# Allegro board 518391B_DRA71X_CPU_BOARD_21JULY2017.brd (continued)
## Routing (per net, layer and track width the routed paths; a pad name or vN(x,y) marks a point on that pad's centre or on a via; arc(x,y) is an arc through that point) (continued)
MCU_CAN0_STB: length 30.2
  TOP w0.127: U37.29 141.26,48.35 v2(141.73,47.88)
  TOP w0.14: v4(129.54,30.35) 129.16,29.97 U46.8
  BOTTOM w0.127: v4(129.54,30.35) 130.12,30.94 135.58,30.94 138.94,34.29 138.94,38.35 140.72,40.13 140.72,41.78 142.11,43.18 142.11,45.46 141.73,45.85 v2(141.73,47.88)
  BOTTOM w0.14: R383.1 v4(129.54,30.35)
MCU_CAN0_TX: length 9
  TOP w0.127: U37.63 129.36,42.85 129.67,42.54 129.67,38.48 128.65,37.46 U46.1
MCU_CAN2_RX: length 5.7
  TOP w0.127: v2(132.46,37.08) 133.1,37.08 134.73,38.72 U37.10
  BOTTOM w0.127: v2(132.46,37.08) RJ27.1
MCU_CAN2_STB: length 24.6
  TOP w0.127: U37.28 141.13,47.85 142.11,46.86 v2(142.15,46.86) ; v4(137.29,28.19) RJ31.1
  BOTTOM w0.127: v4(137.29,28.19) 137.52,28.42 137.52,32.36 139.32,34.16 139.32,37.97 141.07,39.72 141.07,41.5 142.49,42.93 142.49,46.48 142.15,46.82 v2(142.15,46.86)
MCU_CAN2_TX: length 6.5
  TOP w0.127: v2(133.05,37.85) 133.55,38.35 133.86,38.35 134.23,38.73 U37.9
  BOTTOM w0.127: v2(133.05,37.85) 133.05,35.38 RJ28.1
MCU_DBG_RESETN: length 49.3
  TOP w0.127: v2(109.35,31.88) 108.46,30.99 108.46,30.73 107.7,29.97 107.7,28.96 107.19,28.45 107.19,26.54 106.43,25.78 105.41,25.78 104.65,25.02 104.65,23.24 J15.13
  BOTTOM w0.127: v2(109.35,31.88) 110.62,30.61 118.87,30.61 121.41,33.15 134.62,33.15 136.27,34.8 136.27,39.37 135.89,39.75 R349.2
MCU_DCAN1_RX: length 1.8
  BOTTOM w0.127: R371.2 129.54,35.05 RJ27.3
MCU_DCAN1_STB: length 1.1
  TOP w0.127: R426.2 RJ31.3
MCU_DCAN1_TX: length 2.9
  BOTTOM w0.127: R372.2 128.47,34.47 129.72,34.47 129.92,34.67 RJ28.3
MCU_FLMD0: length 51.5
  TOP w0.127: U37.26 v2(141.08,46.85)
  BOTTOM w0.127: J15.4 107.06,34.67 109.22,32.51 120.02,32.51 121.03,33.53 134.37,33.53 135.76,34.92 135.76,37.85 135.13,38.48 135.13,45.85 135.51,46.23 140.46,46.23 v2(141.08,46.85) 140.22,46.85 R332.1
MCU_FLMD1: length 47.5
  TOP w0.127: J15.6 104.65,33.4 104.65,39.5 104.27,39.88 104.27,44.83 106.43,46.99 v2(106.43,47.75)
  LY3 w0.133: v2(106.43,47.75) 116.97,47.75 118.49,46.23 121.41,46.23 122.05,45.59 124.08,45.59 126.11,47.62 128.65,47.62 129.67,48.64 131.95,48.64 v2(132.46,48.13)
  BOTTOM w0.127: R323.2 R322.1 v2(132.46,48.13)
MCU_LIN_EN: length 39.8
  TOP w0.127: 112.27,34.54 v4(112.27,35.98) ; U37.30 v2(141.05,48.85)
  LY3 w0.133: v4(112.27,35.98) 112.27,35.94 112.78,35.43 115.7,35.43 116.08,35.81 123.56,35.81 127.38,39.64 127.38,42.04 128.4,43.05 131.06,43.05 136.86,48.85 v2(141.05,48.85)
  BOTTOM w0.127: R375.1 v4(112.27,35.98)
MCU_P10_9: length 3.9
  TOP w0.127: U37.54 v2(130.3,47.35)
  BOTTOM w0.127: v2(130.3,47.35) 129.52,48.13 R327.2
MCU_P10_10: length 2.4
  TOP w0.127: U37.55 v2(129.65,46.85)
  BOTTOM w0.127: v2(129.65,46.85) 129.39,47.12 R331.2
MCU_P10_13: length 2.6
  TOP w0.127: U37.58 129.3,45.35 v2(129.67,45.72)
  BOTTOM w0.127: R335.2 129.29,46.1 v2(129.67,45.72)
MCU_P10_14: length 2.4
  TOP w0.127: U37.59 129.54,44.85 129.54,44.84 v2(129.64,44.84)
  BOTTOM w0.127: v2(129.64,44.84) 129.4,45.08 R341.2
MCU_PMIC_POWERHOLD: length 112.3
  TOP w0.127: U37.31 141.55,49.35 v2(142.11,49.91) ; Q2.5 v2(161.8,145.41)
  LY4 w0.133: v2(161.8,145.41) 160.4,144.02 160.4,131.44 159.77,130.81 159.77,125.6 158.5,124.33 158.5,121.28 157.86,120.65 157.86,104.65 154.94,101.73 154.56,101.73 153.92,102.36 152.41,102.36 151.64,101.59 151.64,100.97 151.13,100.46 150.37,100.46 149.61,99.69 149.61,95.12 150.24,94.49 150.24,84.96 147.19,81.91 147.19,61.59 145.29,59.69 145.29,53.09 v2(142.11,49.91)
  BOTTOM w0.127: R319.2 141.6,49.4 v2(142.11,49.91)
MCU_RDY: length 47.2
  TOP w0.127: U37.14 136.73,39.33 136.53,39.12 136.53,38.48 v2(136.91,38.1) ; J15.11 104.65,25.78 104.65,27.69 105.28,28.32 106.43,28.32 107.19,29.08 107.19,29.97 107.82,30.61 107.82,31.37 v2(108.39,31.94)
  BOTTOM w0.127: v2(108.39,31.94) 110.24,30.1 119,30.1 121.67,32.77 134.87,32.77 136.91,34.8 v2(136.91,38.1)
MCU_RESETN: length 9
  TOP w0.127: U37.20 v2(141.7,43.85)
  BOTTOM w0.127: v2(141.7,43.85) 140.98,43.85 140.89,43.94 C498.2 R345.1 R349.1
MCU_RLIN30RX: length 2.5
  TOP w0.127: v2(132.97,41.78) 133.24,41.52 U37.7
  BOTTOM w0.127: R356.2 132.72,41.53 v2(132.97,41.78)
MCU_RLIN30TX: length 3.2
  TOP w0.127: U37.6 132.74,41.38 132.33,41.78 v2(131.57,41.78)
  BOTTOM w0.127: R357.2 v2(131.57,41.78)
MCU_RLIN31RX: length 24.1
  TOP w0.127: 113.54,34.54 v4(113.54,35.94) ; U37.56 v2(126.88,46.35)
  LY3 w0.133: v2(126.88,46.35) 126.41,45.88 126.41,41.32 124.55,39.46 122.77,39.46 120.65,37.34 114.94,37.34 v4(113.54,35.94)
  BOTTOM w0.127: R374.2 v4(113.54,35.94)
MCU_RLIN31TX: length 30.1
  TOP w0.127: U37.57 126.49,45.85 v2(125.98,46.35) ; v2(110.11,44.96) 110.11,41.4 108.97,40.26 108.97,36.7 109.73,35.94 109.73,34.54
  BOTTOM w0.127: v2(125.98,46.35) 125.35,45.72 114.81,45.72 114.05,44.96 v2(110.11,44.96)
MCU_SCL: length 35.4
  TOP w0.127: U38.6 v2(108.08,42.16) 108.58,41.66 108.58,40 108.46,39.88 v2(108.46,37.85) ; U37.1 v2(130.24,38.86)
  BOTTOM w0.127: v2(108.08,42.16) R350.2 ; v2(108.46,37.85) 109.85,37.85 110.11,38.1 114.3,38.1 116.79,35.61 117.93,35.61 118.11,35.43 121.79,35.43 124.75,38.39 124.75,39.66 125.9,40.81 128.36,40.81 130.24,38.93 v2(130.24,38.86)
MCU_SDA: length 24.7
  TOP w0.127: U37.64 v2(128.24,41.68) ; U38.5 v2(108.08,40.89)
  BOTTOM w0.127: R351.2 v2(108.08,40.89) 109.6,42.42 114.81,42.42 115.32,41.91 117.73,41.91 118.24,42.42 126.24,42.42 126.97,41.68 v2(128.24,41.68)
MCU_SPI1_SI: length 2.9
  TOP w0.127: U37.53 130.02,47.85 v2(130.3,48.13)
  BOTTOM w0.127: v2(130.3,48.13) R323.1
MCU_TCK: length 41.4
  TOP w0.127: v2(130.3,42.35) 138.06,42.35 138.16,42.25 138.5,42.25 138.6,42.35 U37.17
  BOTTOM w0.127: v2(130.3,42.35) 129.1,41.15 125.86,41.15 124.5,39.79 124.5,38.65 121.67,35.81 118.36,35.81 118.24,35.94 116.97,35.94 114.43,38.48 104.65,38.48 J15.1
MCU_TDI: length 62.2
  TOP w0.127: U37.19 141.05,43.35 v2(141.1,43.31)
  BOTTOM w0.127: J15.7 102.62,29.59 100.71,27.69 100.71,24.89 102.36,23.24 106.43,23.24 107.57,24.38 107.57,26.03 109.51,27.98 119.8,27.98 123.06,31.24 135.38,31.24 138.56,34.42 138.56,38.61 140.34,40.39 R348.2 v2(141.1,43.31)
MCU_TDO: length 48
  TOP w0.127: v2(138.33,42.67) 138.51,42.85 U37.18
  BOTTOM w0.127: v2(138.33,42.67) 137.46,41.81 137.46,39.64 137.67,39.43 137.67,38.73 137.79,38.61 137.79,34.67 135.13,32 122.3,32 119.38,29.08 108.33,29.08 106.55,30.86 104.65,30.86 J15.5
MCU_TMS: length 47.2
  TOP w0.127: v2(138.18,39.05) 137.73,39.49 U37.16
  BOTTOM w0.127: R391.1 101.6,25.78 106.81,25.78 109.47,28.45 119.51,28.45 122.68,31.62 135.25,31.62 138.18,34.54 v2(138.18,39.05) R354.2
MCU_TRSTN: length 46.7
  TOP w0.127: v2(137.03,38.86) 137.23,39.06 U37.15
  BOTTOM w0.127: 101.47,33.53 106.05,33.53 109.98,29.59 119.25,29.59 122.05,32.38 135,32.38 137.41,34.8 137.41,38.48 v2(137.03,38.86) 136.78,39.12 R355.1
MCU_TVD: length 6.6
  TOP w0.305: v2(109.73,33.02) 108.46,33.02 107.19,31.75 107.19,30.86 J15.8
  BOTTOM w0.305: v2(109.73,33.02) R376.1
MCU_WP: length 38.1
  TOP w0.127: v2(131.06,45.97) 132.44,47.35 U37.27 ; U38.7 v2(108.08,43.43)
  BOTTOM w0.127: v2(131.06,45.97) 131.06,44.2 130.3,43.43 126.49,43.43 126.11,43.81 123.19,43.81 122.56,43.18 118.24,43.18 117.35,42.29 115.59,42.29 114.45,43.43 v2(108.08,43.43) R347.1
MCU_X1: length 6.8
  TOP w0.127: X1.2 v2(143.77,47.49) 142.63,46.35 U37.25
  BOTTOM w0.127: C493.1 144.52,47.49 v2(143.77,47.49)
MCU_X2: length 2.8
  TOP w0.127: U37.24 141.73,45.85 141.86,45.72 R130.2
MDIO_MDCLK: length 54.3
  TOP w0.127: v2(116.71,42.8) 117.12,42.39 U40.1 ; U27.D10 v1(95.24,78.53)
  LY3 w0.133: v2(116.71,42.8) 116.2,43.31 109.35,43.31 108.8,43.86 103.34,43.86 v2(103.25,43.94)
  BOTTOM w0.127: v2(103.25,43.94) 102.83,44.36 102.83,46.41 101.98,47.27 101.98,49.15 98.04,53.09 98.04,57.15 98.93,58.04 98.93,59.56 98.04,60.45 98.04,68.2 96.31,69.93 96.31,74.11 94.87,75.55 94.87,78.17 v1(95.24,78.53)
MDIO_MDIO: length 52.1
  TOP w0.127: U40.36 v2(118.39,44.04) ; U27.C10 v1(95.24,77.88)
  LY3 w0.133: v2(102.36,53.47) 102.62,53.72 102.62,58.42 101.98,59.05 101.98,68.83 98.09,72.73 98.09,73.87 95.63,76.33 95.63,77.49 v1(95.24,77.88)
  BOTTOM w0.127: v2(102.36,53.47) 105.03,50.8 105.41,50.8 107.31,48.89 107.31,46.35 108.08,45.59 108.58,45.59 109.98,44.2 114.05,44.2 115.19,45.34 117.35,45.34 117.73,44.96 117.73,44.7 v2(118.39,44.04) 118.42,44.07 R344.2
MMC2_CLK: length 27.2
  TOP w0.127: R99.1 106.05,64.05 105.9,63.9 105.56,63.9 105.41,63.75 105.41,63.54 105.56,63.39 105.9,63.39 106.05,63.25 106.05,63.04 105.9,62.89 105.56,62.89 105.41,62.74 105.41,62.53 105.56,62.38 105.9,62.38 v2(107.82,60.45)
  LY3 w0.133: v2(107.82,60.45) 111.89,60.45 112.9,59.44 123.32,59.44 v2(123.44,59.56)
  BOTTOM w0.127: v2(123.44,59.56) R299.1 R300.2
MMC2_CMD: length 45.7
  TOP w0.127: U27.A6 97.51,75.84 100.84,72.51 100.84,71.37 104.27,67.94 104.27,62.1 v2(105.41,60.96) ; U31.P5 v2(123.21,60.41)
  LY3 w0.133: v2(123.21,60.41) 122.74,59.94 113.03,59.94 112.01,60.96 109.33,60.96 109.18,61.12 109.18,62.07 109.02,62.23 108.8,62.23 108.64,62.07 108.64,61.12 108.49,60.96 108.27,60.96 108.11,61.12 108.11,62.07 107.95,62.23 107.73,62.23 107.58,62.07 107.58,61.12 107.42,60.96 107.2,60.96 107.04,61.12 107.04,62.07 106.89,62.23 106.67,62.23 106.51,62.07 106.51,61.12 106.35,60.96 v2(105.41,60.96)
  BOTTOM w0.127: 124.08,60.45 123.25,60.45 v2(123.21,60.41)
MMC2_DAT0: length 45.3
  TOP w0.127: U27.D7 v1(97.19,78.53) ; v2(117.28,68.58) 118.32,68.58 118.47,68.73 118.47,70.72 118.62,70.87 118.83,70.87 118.98,70.72 118.98,68.73 119.38,68.33 119.38,67.04 119.23,66.89 117.43,66.89 117.28,66.74 117.28,66.53 117.43,66.38 119.23,66.38 119.38,66.23 119.38,66.02 119.23,65.87 117.43,65.87 117.28,65.72 117.28,65.47 118.34,64.41 v2(120.2,64.41) U31.K2
  LY3 w0.133: v1(97.19,78.53) 97.6,78.12 97.6,76.89 102.61,71.89 103.24,71.89 106.17,68.96 116.9,68.96 v2(117.28,68.58)
  BOTTOM w0.127: R273.2 120.18,64.39 v2(120.2,64.41)
MMC2_DAT1: length 45.8
  TOP w0.102: 97.84,78.53 v1(97.84,78.53)
  TOP w0.127: v2(115.06,69.51) 115.66,69.51 115.95,69.21 115.95,67.1 116.1,66.95 116.56,66.95 116.71,66.8 116.71,66.59 116.56,66.44 116.1,66.44 115.95,66.29 115.95,66.08 116.1,65.93 116.56,65.93 116.71,65.79 116.71,65.58 116.56,65.43 116.1,65.43 115.95,65.28 115.95,65.02 116.61,64.37 117.58,64.37 117.73,64.22 117.73,64.01 117.58,63.86 116.61,63.86 116.46,63.71 116.46,63.46 116.61,63.31 118.98,63.31 119.13,63.16 119.13,62.95 118.98,62.8 116.61,62.8 116.46,62.65 116.46,61.85 116.9,61.41 v2(120.2,61.41) U31.N2 ; U27.C6 97.84,78.53
  LY3 w0.133: v1(97.84,78.53) 97.84,78.53 97.84,77.17 102.74,72.26 103.38,72.26 106.16,69.48 115.03,69.48 v2(115.06,69.51)
  BOTTOM w0.127: v2(120.2,61.41) 120.14,61.47 R271.2
MMC2_DAT2: length 45.1
  TOP w0.127: v2(105.41,66.55) 105.41,67.56 101.35,71.63 101.35,72.72 98.16,75.91 U27.A5 ; U31.K3 v2(121.2,64.41)
  LY3 w0.133: v2(105.41,66.55) 106.05,65.91 106.34,65.91 106.49,66.07 106.49,66.77 106.65,66.93 106.87,66.93 107.03,66.77 107.03,66.07 107.18,65.91 107.7,65.91 107.86,65.74 108.1,65.74 108.26,65.9 108.26,66.77 108.41,66.93 108.63,66.93 108.79,66.77 108.79,65.9 108.95,65.74 109.17,65.74 109.32,65.9 109.32,66.77 109.48,66.93 109.7,66.93 109.86,66.77 109.86,65.9 110.01,65.74 110.23,65.74 110.39,65.9 110.39,66.77 110.55,66.93 110.77,66.93 110.92,66.77 110.92,65.9 111.08,65.74 113.45,65.74 114.3,64.9 115.01,64.9 115.17,65.05 115.17,66.39 115.32,66.55 115.55,66.55 115.7,66.39 115.7,65.05 115.86,64.9 116.08,64.9 116.23,65.05 116.23,66.39 116.39,66.55 116.61,66.55 116.77,66.39 116.77,65.05 116.92,64.9 120.72,64.9 v2(121.2,64.41)
  BOTTOM w0.127: v2(121.2,64.41) 121.23,64.39 R269.2
MMC2_DAT3: length 44.9
  TOP w0.102: U27.B6 97.84,77.23 97.84,76.17
  TOP w0.127: v2(104.78,64.39) 104.78,67.82 101.09,71.5 101.09,72.62 97.84,75.87 97.84,76.17 ; U31.N3 v2(121.2,61.41)
  LY3 w0.133: v2(104.78,64.39) 104.78,63.02 104.62,62.86 103.53,62.86 103.38,62.7 103.38,62.48 103.53,62.33 104.62,62.33 104.78,62.17 104.78,62.11 104.91,61.98 105.66,61.98 106.36,62.67 106.36,64.23 106.52,64.39 106.74,64.39 106.9,64.23 106.9,63.15 107.05,62.99 107.27,62.99 107.43,63.15 107.43,64.23 107.59,64.39 108.58,64.39 110.87,62.1 115.57,62.1 116.33,61.34 118.24,61.34 118.75,61.85 120.76,61.85 v2(121.2,61.41)
  BOTTOM w0.127: v2(121.2,61.41) 121.26,61.47 R291.2
MMC2_DAT4: length 46.4
  TOP w0.127: U31.N8 v2(127.21,61.41) ; v2(108.58,59.82) 108.58,60.79 109.14,61.34 109.14,61.55 108.99,61.7 108.78,61.7 108.23,61.15 108.02,61.15 107.87,61.3 107.87,61.51 108.42,62.06 108.42,62.27 108.27,62.42 108.06,62.42 107.51,61.87 107.3,61.87 106.55,62.61 106.55,68.24 98.81,75.98 U27.A4
  LY3 w0.133: v2(127.21,61.41) 127.2,61.41 124.71,58.93 112.78,58.93 111.89,59.82 v2(108.58,59.82)
  BOTTOM w0.127: R289.2 127.02,61.59 v2(127.21,61.41)
MMC2_DAT5: length 43.5
  TOP w0.127: U27.E7 v1(97.19,79.18) ; U31.K8 v2(127.21,64.41)
  LY3 w0.133: v1(97.19,79.18) 96.82,78.81 96.82,76.66 99.19,74.3 99.19,73.79 105.03,67.94 117.16,67.94 117.31,67.79 117.31,66.45 117.47,66.29 117.69,66.29 117.85,66.45 117.85,67.79 118,67.94 118.24,67.94 120.14,66.04 121.54,66.04 123.19,64.39 127.19,64.39 v2(127.21,64.41)
  BOTTOM w0.127: v2(127.21,64.41) 127.06,64.26 126.36,64.26
MMC2_DAT6: length 44.6
  TOP w0.127: v2(106.3,70.4) 108.2,68.49 v2(108.2,63.88) ; U27.D6 v1(97.84,79.18) ; U31.N9 v2(128.21,61.41)
  LY3 w0.133: v2(106.3,70.4) 105.75,70.4 103.51,72.64 102.87,72.64 98.12,77.4 98.12,78.18 98.3,78.36 98.3,78.74 97.85,79.18 v1(97.84,79.18) ; v2(128.21,61.41) 127.79,61.83 126.73,61.83 125.86,60.96 114.68,60.96 114.43,60.71 112.9,60.71 112.01,61.59 110.49,61.59 v2(108.2,63.88)
  BOTTOM w0.127: v2(128.21,61.41) 128.28,61.34 R270.2
MMC2_DAT7: length 43.4
  TOP w0.102: 98.49,77.88 v1(98.49,77.88) 98.49,77.88
  TOP w0.127: U27.C5 v1(98.49,77.88) ; U31.K9 v2(128.21,64.41)
  LY3 w0.133: v1(98.49,77.88) 98.49,77.53 103,73.02 103.63,73.02 105.66,70.99 109.04,70.99 109.17,70.86 111.76,70.86 112.69,69.94 113.24,69.94 113.92,70.61 117.22,70.61 117.37,70.77 117.37,71.47 117.53,71.63 117.75,71.63 117.91,71.47 117.91,70.77 118.06,70.61 118.28,70.61 118.44,70.77 118.44,71.47 118.6,71.63 118.82,71.63 118.97,71.47 118.97,70.77 119.13,70.61 119.38,70.61 119.63,70.36 119.63,67.18 120.4,66.42 121.92,66.42 123.44,64.9 127.72,64.9 v2(128.21,64.41)
  BOTTOM w0.127: v2(128.21,64.41) 128.23,64.39 R268.2
MMC_PWR_ON: length 232.5
  TOP w0.127: U70.3 159,131.19 v2(159.51,131.7) 160.78,131.7 R412.2 ; v1(86.14,82.43) U27.K23
  LY3 w0.133: v2(131.57,97.96) 130.64,97.96 129.79,98.81 105.54,98.81 105.03,99.31 98.42,99.31 89.41,108.33 58.04,108.33 56.64,109.73 47.88,109.73 46.1,107.95 46.1,101.98 45.34,101.22 45.34,95.5 46.48,94.36 46.48,72.77 47.37,71.88 63.25,71.88 64.94,73.57 67.48,73.57 70.36,76.45 73.66,76.45 76.58,79.38 83.08,79.38 84.4,80.7 v1(86.14,82.43)
  LY4 w0.133: v2(159.51,131.7) 159.51,132.08 158.75,132.84 142.24,132.84 131.15,121.75 131.15,101.39 131.57,100.97 v2(131.57,97.96)
NEO_RESETN: length 89.1
  TOP w0.127: U27.H3 v1(99.79,81.78) ; U25.8 v2(167.04,91.49)
  LY3 w0.133: v2(163.32,74.68) 162.95,75.05 155.45,75.05 154.56,75.95 143.89,75.95 143.38,75.44 138.81,75.44 137.79,76.45 137.29,76.45 136.78,75.95 136.64,75.95 136.63,75.95 134.51,75.95 134.51,75.95 134.37,75.95 133.74,75.32 128.14,75.32 127,76.45 122.17,76.45 120.52,78.1 119.13,78.1 118.24,78.99 113.66,78.99 112.78,78.1 106.68,78.1 104.39,80.39 101.98,80.39 100.59,81.78 v1(99.79,81.78)
  LY4 w0.133: v2(163.32,74.68) 163.32,84.33 167.04,88.05 v2(167.04,91.49)
  BOTTOM w0.127: v2(167.04,91.49) 167,91.52 R238.2
NEO_TIMEPULSE: length 128.8
  TOP w0.127: v2(71.78,75.12) 71.67,75.01 R79.2 ; v2(152.27,71.25) 156.59,75.56 165.1,75.56 R68.2 R69.1
  LY3 w0.133: v2(152.27,71.25) 152.27,65.91 148.21,61.85 143.38,61.85 142.88,62.36 137.92,62.36 136.78,61.21 134.11,61.21 131.35,58.45 112.62,58.45 111.88,59.19 109.86,59.19 107.57,56.9 107.57,54.1 105.45,51.99 97.87,51.99 93.85,56.01 93.85,63.12 90.3,66.67 87.88,66.67 87.25,67.31 86.11,67.31 85.85,67.56 76.58,67.56 75.44,68.71 75.44,72.26 73.91,73.79 73.11,73.79 v2(71.78,75.12)
NFAULT: length 151.6
  TOP w0.102: 101.52,81.14 100.44,81.14 U27.H2
  TOP w0.127: D11.2 v2(41.02,104.39) ; v2(116.2,77.22) 116.04,77.38 114,77.38 113.67,77.05 106.06,77.05 105.39,77.72 105.39,77.72 105.26,77.85 101.97,81.14 101.52,81.14 ; U28.26 v2(34.35,92.01)
  LY3 w0.133: v2(93.34,111.12) 100.08,104.39 v2(115.19,104.39)
  LY4 w0.133: v2(115.19,104.39) 115.19,82.42 115.7,81.92 115.7,77.72 v2(116.2,77.22) ; v2(93.34,111.12) 92.58,111.89 82.04,111.89 79.12,114.81 70.61,114.81 68.07,112.27 62.74,112.27 62.48,112.01 55.88,112.01 54.99,112.9 48.91,112.9 46.23,110.22 46.23,109.73 42.42,105.92 41.78,105.92 41.02,105.16 v2(41.02,104.39) 41.91,103.5 41.91,93.85 40.39,92.33 35.05,92.33 34.73,92.01 v2(34.35,92.01)
NMUTE: length 141.7
  TOP w0.127: U27.K5 v1(98.49,82.43) ; U28.25 34.86,91.38 v2(35.05,91.57)
  LY3 w0.133: v2(92.46,111.12) 99.69,103.89 v2(114.55,103.89)
  LY4 w0.133: v2(114.55,103.89) 114.55,102.62 114.18,102.24 114.18,82.68 113.66,82.17 101.6,82.17 100.71,83.06 99.11,83.06 v1(98.49,82.43) ; v2(92.46,111.12) 92.08,111.51 81.66,111.51 78.87,114.3 70.74,114.3 67.18,110.74 53.05,110.74 52.54,111.25 49.91,111.25 49.66,111.51 47.88,111.51 46.74,110.36 46.74,109.73 43.69,106.68 43.69,105.66 42.28,104.26 42.28,93.59 40.64,91.95 35.43,91.95 v2(35.05,91.57)
NSTANDBY: length 139.3
  TOP w0.127: v1(97.84,82.43) U27.K6 ; v2(34.42,90.8) 34.35,90.74 U28.24
  LY3 w0.133: v2(113.92,103.38) 99.19,103.38 v2(91.57,111)
  LY4 w0.133: v1(97.84,82.43) 98.72,83.31 100.96,83.31 101.73,82.55 105.03,82.55 105.66,83.19 112.01,83.19 112.39,82.8 113.66,82.8 113.92,83.06 v2(113.92,103.38) ; v2(91.57,111) 81.41,111 78.61,113.79 70.99,113.79 67.52,110.32 48.88,110.32 42.54,103.99 42.54,93.22 40.89,91.57 36.07,91.57 35.31,90.8 v2(34.42,90.8)
NTRST: length 3.9
  TOP w0.127: J14.9 120.18,52.66 v2(120.52,52.32)
  BOTTOM w0.127: RJ26.3 v2(120.52,52.32) 120.65,52.45 R312.2
NWARN: length 156.5
  TOP w0.127: v2(34.8,92.96) 34.48,92.65 U28.27 ; v1(97.84,81.78) U27.H6 ; D10.2 v2(41.02,106.43)
  LY3 w0.133: v2(94.23,111.12) 100.46,104.9 v2(115.76,104.9) ; v1(97.84,81.78) 98.72,80.9 99.95,80.9 101.6,79.25 103.76,79.25 106.05,76.96 113.66,76.96 114.43,77.72 v2(117.6,77.72)
  LY4 w0.133: v2(117.6,77.72) 116.46,78.87 116.46,82.68 116.2,82.93 116.2,84.96 115.45,85.72 115.45,103.32 115.76,103.63 v2(115.76,104.9) ; v2(34.8,92.96) 39.88,92.96 41.4,94.49 41.4,102.11 40.39,103.12 40.39,105.79 v2(41.02,106.43) 42.42,106.43 45.72,109.73 45.72,110.08 48.92,113.28 68.45,113.28 70.49,115.32 79.38,115.32 82.42,112.27 93.09,112.27 v2(94.23,111.12)
OUT1M: length 5.4
  TOP w0.406: U28.32 19.69,91.38 19.1,91.96 C87.1
OUT1P: length 5.4
  TOP w0.406: U28.34 19.63,90.11 19.1,89.58 C93.1
OUT2M: length 3.3
  TOP w0.406: U28.38 v2(21.91,87.57)
  TOP w0.508: v2(20.32,87.38) 20.35,87.35 v2(21.11,87.35)
  TOP w0.635: v2(21.91,87.57) 21.69,87.35 v2(21.11,87.35)
OUT2P: length 3.3
  TOP w0.406: v2(21.91,86.19) 22.01,86.3 U28.40
  TOP w0.762: v2(21.91,86.19) 21.81,86.19 21.72,86.11 v2(21.08,86.11) 20.45,86.11 v2(20.32,86.23)
OUT3M: length 5.1
  TOP w0.406: U28.45 21.91,83.12 21.84,83.06 19.91,83.06 19.1,83.87 C97.1
OUT3P: length 5.2
  TOP w0.406: U28.47 19.94,81.85 19.1,81.01 C107.1
OUT4M: length 3.3
  TOP w0.406: U28.51 v2(21.91,79.31)
  TOP w0.508: v2(20.45,79.12) 20.56,79.01 v2(21.21,79.01)
  TOP w0.635: v2(21.91,79.31) 21.6,79.01 v2(21.21,79.01)
OUT4P: length 3.4
  TOP w0.406: U28.53 v2(21.91,78.04)
  TOP w0.762: v2(20.37,78.1) 20.63,77.84 v2(21.08,77.84) 21.71,77.84 v2(21.91,78.04)
PG1_PMIC: length 67.5
  TOP w0.127: 74.8,48.77 TP41.1 75.29,50.53 77.38,50.53 77.39,50.53 79.54,50.53 79.54,50.53 v2(81.13,50.53) 81.41,50.53 81.93,51.05 82.58,51.05 83.47,51.95 U32.27
  LY3 w0.133: v2(81.13,50.53) 81.9,50.53 83.29,51.92 87.66,51.92 87.87,51.7 87.87,51.07 89.66,49.28 95.88,49.28 97.04,50.43 120.15,50.43 120.4,50.67 121.79,50.67 122.3,51.18 132.46,51.18 v2(133.22,50.42)
  BOTTOM w0.127: R316.1 v2(133.22,50.42)
PG_LM5141: length 179.6
  TOP w0.127: 73.15,111.76 v2(74.42,111.76)
  TOP w0.203: U18.21 v2(76.59,125.22) ; U42.6 91.31,34.29 v2(92.2,33.4)
  LY3 w0.133: v2(41.87,67.44) 41.91,67.44 42.93,66.42 43.43,66.42 44.45,65.41 45.72,65.41 49.4,61.72 53.72,61.72 v2(54.99,60.45) ; v2(74.42,111.76) 74.42,113.16 76.2,114.94 TP12.1 76.2,124.83 v2(76.59,125.22)
  LY4 w0.133: v2(74.42,111.76) 71.75,109.09 50.55,109.09 47.37,105.92 47.37,104.9 44.02,101.55 44.02,96.55 44.2,96.37 44.2,87.12 43.69,86.61 43.69,81.28 44.44,80.52 44.44,75.05 41.87,72.48 v2(41.87,67.44) ; v2(78.87,135.76) 76.96,133.86 76.96,125.6 76.59,125.23 v2(76.59,125.22)
  BOTTOM w0.127: Q11.2 v2(78.87,135.76) ; v2(92.2,33.4) 90.04,33.4 87.5,30.86 67.69,30.86 56.9,41.66 56.9,57.53 54.99,59.44 v2(54.99,60.45)
  BOTTOM w0.203: v2(76.59,125.22) 76.58,125.22 R217.1
PG_LM5175: length 253.8
  TOP w0.127: v2(132.21,92.16) 132.63,92.58 134.62,92.58 135,92.2 144.36,92.2 v2(144.74,91.82) ; v2(136.92,18.58) 136.92,13.95 138.56,12.32 141.49,12.32 141.84,12.67 U51.3 ; U43.3 v2(145.68,38.86)
  TOP w0.203: TP9.1 v2(58.55,121.28) 56.26,121.28 55.89,120.91 U19.17 ; C63.2 R40.2 v2(58.55,117.35)
  LY3 w0.133: 94.91,138.3 v2(94.91,143.51) ; 94.91,138.3 97.41,138.3 102.74,132.97 v2(132.72,132.97) ; 94.91,138.3 93.51,136.91 70.99,136.91 67.06,132.97 67.06,131.95 60.83,125.73 60.83,124.59 TP9.1 v2(58.55,121.28)
  LY4 w0.133: v2(146.69,76.45) 145.8,77.34 145.8,80.26 144.14,81.91 144.14,90.04 144.74,90.64 v2(144.74,91.82) ; v2(132.21,92.16) 132.21,93.85 131.06,95 131.06,95.88 130.68,96.27 130.68,100.33 130.43,100.58 130.43,122.43 132.72,124.71 v2(132.72,132.97)
  BOTTOM w0.127: v2(136.92,18.58) 140.59,22.25 140.59,24.38 141.35,25.15 141.35,31.62 142.96,33.24 142.96,36.14 v2(145.68,38.86) 145.68,39.99 143.22,42.46 143.22,48.22 144.53,49.53 144.53,60.2 148.34,64.01 148.34,65.28 149.22,66.17 149.22,70.23 147.32,72.14 147.32,75.82 v2(146.69,76.45) ; R208.1 94.49,143.93 v2(94.91,143.51)
  BOTTOM w0.203: v2(58.55,121.28) v2(58.55,117.35)
PG_LM53603: length 46
  TOP w0.127: U15.8 95.57,139.25 TP6.1 ; U11.7 v2(126.87,146.81) 127.25,146.43 R7.2
  LY3 w0.133: v2(119.25,133.73) 102.87,133.73 97.41,139.19 TP6.1
  LY4 w0.133: v2(119.25,133.73) 126.62,141.1 126.62,145.03 126.87,145.29 v2(126.87,146.81)
PM1_SCL: length 166.7
  LY3 w0.133: v2(145.17,93.22) 145.16,93.22 143,95.38 139.19,95.38 136.4,98.17 132.84,98.17 131.44,99.57 108.97,99.57 106.55,101.98 97.79,101.98 89.66,110.11 84.84,110.11 82.42,112.52 v2(82.42,113.28) ; v2(78.61,147.19) 76.83,147.19 75.44,148.59 47.12,148.59 44.45,145.92 v2(34.92,145.92)
  LY4 w0.133: v2(78.61,147.19) 78.61,144.4 76.83,142.62 76.83,137.8 75.06,136.02 75.06,119.89 79.12,115.82 79.88,115.82 v2(82.42,113.28)
  BOTTOM w0.127: v2(78.61,147.19) R414.1 U71.2 ; U74.5 34.18,139.84 34.92,140.59 v2(34.92,145.92) ; J21.36 v2(145.17,93.22)
PM1_SDA: length 161.4
  LY3 w0.133: v2(78.74,140.84) 68.33,140.84 61.05,148.12 47.41,148.12 44.45,145.16 v2(34.42,145.16) ; v2(83.25,113.35) 85.98,110.62 89.92,110.62 98.17,102.36 106.81,102.36 109.22,99.95 131.7,99.95 133.1,98.55 136.65,98.55 139.45,95.76 143.64,95.76 v2(146.17,93.23)
  LY4 w0.133: v2(78.74,140.84) 78.74,140.33 78.64,140.23 78.64,138.84 76.33,136.52 76.33,125.98 75.82,125.48 75.82,120.01 79.5,116.33 80.26,116.33 v2(83.25,113.35)
  BOTTOM w0.127: U74.4 34.17,140.34 34.42,140.59 v2(34.42,145.16) ; U72.2 R415.1 v2(78.74,140.84) ; J21.38 v2(146.17,93.23)
PM_BRD_PWR_OFF: length 101.3
  LY3 w0.133: v2(140.17,92.96) 140.17,93.76 136.14,97.79 132.59,97.79 131.19,99.19 108.71,99.19 106.3,101.6 97.28,101.6 89.28,109.6 84.2,109.6 79.57,114.24 v2(79.57,117.03)
  LY4 w0.133: v2(79.57,117.03) 77.09,119.51 77.09,122.81 77.34,123.06 77.34,133.35 80.14,136.14 80.14,137.54 79.12,138.56 v2(79.12,139.95)
  BOTTOM w0.127: R423.1 v2(140.17,92.96) 140.17,93.13 140.16,93.14 J21.26 ; v2(79.12,139.95) 78.87,139.7 Q11.5
PM_RESETN: length 138.1
  LY3 w0.133: v2(110.24,63.88) 111.51,62.61 121.67,62.61 121.92,62.86 124.08,62.86 124.33,62.61 134.51,62.61 134.51,62.6 136.76,62.6 136.77,62.61 136.91,62.61 137.41,63.12 143,63.12 143.75,62.37 144.79,62.37 v2(145.03,62.61)
  LY4 w0.133: v2(110.24,63.88) 109.79,63.44 77.28,63.44 75.56,61.72 v2(67.18,61.72) ; v2(141.16,93.22) 141.16,91.25 141.35,91.06 141.35,89.28 141.16,89.09 141.16,82.48 144.4,79.25 144.4,76.07 145.82,74.65 145.82,70.63 145.46,70.27 145.46,63.03 v2(145.03,62.61)
  BOTTOM w0.127: J21.28 v2(141.16,93.22) ; R402.2 70.61,79.5 67.96,76.85 64.86,73.75 64.86,71.67 65.28,71.25 65.28,69.98 66.8,68.45 66.8,62.1 v2(67.18,61.72)
PMIC_ADCIN1: length 3
  TOP w0.127: R115.1 90.77,53.88 U32.38
PMIC_ADCIN2: length 2.7
  TOP w0.127: R112.1 91.41,54.38 U32.39
PMIC_BOOT: length 3
  TOP w0.127: R106.2 78.91,57.82 R107.2 79.92,57.66 80.14,57.66 80.41,57.38 U32.16
PMIC_EN: length 147.9
  TOP w0.127: v2(43.43,59.05) 43.43,62.74 41.53,64.64 41.53,66.17 41.87,66.51 v2(41.87,66.55) ; v2(79.63,110.49) SW2.1 81.66,110.49 81.91,110.74 81.91,111.51 81.66,111.76 80.77,111.76
  TOP w0.254: U32.15 80.55,57.88 v2(80.52,57.91) ; U39.3 69.21,40.52 v2(69.34,40.39)
  LY3 w0.133: v2(69.34,40.39) 67.69,42.04 67.69,45.47 67.35,45.81 67.35,50.85 67.06,51.14 v2(67.06,54.48) 64.26,54.48 62.48,56.26 61.34,56.26 60.33,57.28 50.29,57.28 49.53,56.52 45.97,56.52 v2(43.43,59.05)
  LY4 w0.133: v2(80.52,57.91) 78.61,57.91 78.23,58.29 72.12,58.29 71.61,57.78 70.36,57.78 v2(67.06,54.48) ; v2(79.63,110.49) 77.86,108.72 51.2,108.72 51.19,108.71 50.6,108.71 47.75,105.87 47.75,104.39 46.1,102.74 46.1,101.51 44.28,99.69 44.28,96.65 44.7,96.23 44.7,73.91 42.29,71.5 42.29,66.97 v2(41.87,66.55)
  BOTTOM w0.127: R433.2 v2(79.63,110.49)
PMIC_GPIO_2: length 4.5
  TOP w0.127: TP35.1 88.27,61 87.47,60.2 U32.2
PMIC_GPIO_4: length 4.2
  TOP w0.127: U32.1 87.97,60.15 89.66,61.85 TP37.1
PMIC_POWERHOLD: length 110.9
  TOP w0.127: R41.1 71.5,111.25 71.37,111.12 71.37,110.53 R422.1 SW2.4 v2(74.3,110.49) ; Q2.3 v2(162.45,141.87)
  LY3 w0.133: v2(162.45,141.87) 162.43,141.86 162.43,140.33 156.84,134.75 142.75,134.75 137.16,129.16 130.56,129.16 123.57,122.17 v2(106.17,122.17)
  LY4 w0.133: v2(106.17,122.17) 106.17,117.98 104.27,116.08 104.27,115.19 99.82,110.74 97.79,110.74 97.03,109.98 81.03,109.98 80.01,111 78.87,111 78.36,110.49 v2(74.3,110.49)
PMIC_REGEN1_3V3_OD: length 232.4
  TOP w0.127: U19.1 v2(48.01,114.05) ; U48.3 92.33,28.95 92.08,29.21 81.66,29.21 v2(78.49,32.38) ; v2(81.15,61.59) 81.91,60.83 81.91,59.79 82.04,59.66 U32.12 ; U49.5 v2(74.88,25.83) ; v2(74.55,33.15) 74.88,33.48 U41.5
  TOP w0.254: v2(101.73,116.59) 101.86,116.72 U20.3
  LY3 w0.133: v2(45.4,104.46) 45.4,111.44 v2(48.01,114.05) ; v2(74.88,25.83) 74.55,26.16 v2(74.55,33.15) 73.28,33.15 69.98,36.45 69.98,42.12 68.37,43.73 68.37,54.05 v2(67.06,55.37) ; v2(40.64,66.8) 41.4,66.04 43.31,66.04 44.32,65.02 45.34,65.02 49.15,61.21 v2(51.94,61.21)
  LY4 w0.133: v2(40.64,66.8) 40.64,68.83 41.15,69.34 41.15,74.8 43.43,77.08 43.43,87.5 43.76,87.83 43.76,102.81 v2(45.4,104.46) 50.41,109.46 71.23,109.46 74.04,112.27 79.38,112.27 81.15,110.49 96.9,110.49 101.73,115.32 v2(101.73,116.59) ; v2(81.15,61.59) 79.72,60.16 77.05,60.16 76.2,59.31 71.86,59.31 71.48,58.93 70.61,58.93 v2(67.06,55.37)
  BOTTOM w0.127: v2(67.06,55.37) 65.79,56.64 62.99,56.64 62.23,57.4 61.43,57.4 60.96,57.87 60.96,58.29 56.77,62.48 53.21,62.48 v2(51.94,61.21) ; v2(74.55,33.15) 75.31,32.38 v2(78.49,32.38) 83.69,37.59 R378.1 TP50.1
PMIC_SCLK_OUT: length 6.5
  TOP w0.127: TP34.1 90.17,63.88 90.17,61.47 89.79,61.09 89.79,59.56 89.11,58.88 U32.48
SD_CLK: length 24.1
  LY3 w0.133: v2(150.5,113.66) 149.86,113.03 147.07,113.03 145.8,114.3 145.8,122.43 144.91,123.32 144.91,127.89 v2(143.13,129.67)
  BOTTOM w0.127: v2(150.5,113.66) 150.71,113.45 RU1.14 ; R406.1 v2(143.13,129.67)
SD_CMD: length 21.6
  LY3 w0.133: v2(148.76,113.62) 148.76,114.39 147.07,116.08 147.07,118.62 146.3,119.38 146.3,122.68 145.29,123.7 145.29,128.78 143.26,130.81 v2(143.13,130.81)
  BOTTOM w0.127: R405.1 v2(143.13,130.81) ; RU1.11 v2(148.76,113.62)
SD_D0: length 23.3
  LY3 w0.133: v2(143.13,128.27) 144.53,126.87 144.53,108.84 144.75,108.61 v2(144.75,108.2)
  BOTTOM w0.127: RU2.2 v2(144.75,108.2) ; R407.1 v2(143.13,128.27)
SD_D1: length 22.1
  LY3 w0.133: v2(143.13,127) 143.76,126.36 143.76,123.44 143.26,122.94 143.26,108.28 v2(142.8,107.82)
  BOTTOM w0.127: RU2.5 v2(142.8,107.82) ; R408.1 v2(143.13,127)
SD_D2: length 32.4
  LY3 w0.133: v2(151.36,108.2) 150.88,108.69 150.88,111 151.38,111.51 151.38,115.82 150.88,116.33 150.88,118.36 148.21,121.03 148.21,123.32 147.7,123.82 147.7,129.67 144.02,133.35 v2(143,133.35)
  BOTTOM w0.127: RU1.2 v2(151.36,108.2) ; R403.1 v2(143,133.35)
SD_D3: length 31.1
  LY3 w0.133: v2(149.41,107.95) 149.61,108.15 149.61,111.12 151,112.52 151,114.55 149.61,115.95 149.61,118.87 146.81,121.67 146.81,122.94 146.43,123.32 146.43,129.92 144.14,132.21 v2(143.13,132.21)
  BOTTOM w0.127: RU1.5 v2(149.41,107.95) ; R404.1 v2(143.13,132.21)
SIL_INTB_CHIP0: length 95.4
  TOP w0.127: U36.39 v2(35.5,52.78) ; U27.F3 v1(99.79,79.83)
  LY4 w0.133: v2(53.47,61.21) 53.72,61.47 65.42,61.47 66.37,62.42 72.47,62.42 74.56,64.52 97.16,64.52 100.2,67.56 100.2,79.42 v1(99.79,79.83)
  BOTTOM w0.127: v2(53.47,61.21) 53.72,60.96 53.72,53.34 54.48,52.58 54.48,51.69 53.59,50.8 51.82,50.8 50.04,52.58 44.2,52.58 44,52.78 v2(35.5,52.78) 34.11,52.78 R313.1
SIL_INTB_CHIP1: length 76.5
  TOP w0.127: U27.G4 v1(99.14,80.48) ; U34.19 52.13,51.3 v2(52.13,51.3) 52.2,51.3 52.2,51.3 52.95,51.3 R122.1
  LY4 w0.133: v2(52.7,60.83) 52.7,61.34 53.18,61.82 65.4,61.82 66.26,62.68 72.36,62.68 74.45,64.78 97.05,64.78 99.94,67.67 99.94,78.37 99.42,78.89 99.42,80.21 v1(99.14,80.48)
  BOTTOM w0.127: v2(52.7,60.83) 53.38,60.16 53.38,51.85 52.83,51.3 v2(52.13,51.3)
SIL_RSTB_CHIP0: length 143.9
  TOP w0.127: v1(99.79,83.73) U27.L3 ; U36.33 v2(35.43,49.78)
  LY3 w0.133: v2(35.43,49.78) 35.43,50.67 32.51,53.59 32.51,55.5 33.27,56.26 33.27,58.17 34.04,58.93 37.46,58.93 38.99,60.45 49.53,60.45 49.91,60.07 51.18,60.07 51.43,60.32 52.96,60.32 53.59,59.69 59.44,59.69 65.28,65.53 69.6,65.53 71.37,63.75 71.37,62.48 72.33,61.53 79.06,61.53 v2(79.76,62.23) ; v2(117.47,82.55) 114.05,82.55 112.78,81.28 106.17,81.28 105.16,82.3 102.11,82.3 100.67,83.73 v1(99.79,83.73)
  LY4 w0.133: v2(79.76,62.23) 80.3,62.78 82.39,62.78 82.67,62.49 115.96,62.49 119,65.53 119,81.03 v2(117.47,82.55)
  BOTTOM w0.127: v2(35.43,49.78) 34.17,49.78 34.16,49.78
SIL_RSTB_CHIP1: length 103.1
  TOP w0.127: U34.13 v2(52.32,48.31) 53.04,48.31 R126.1 ; U27.G1 101.94,80.81 106.03,76.72 113.93,76.72 114.17,76.96 v2(114.81,76.96)
  LY4 w0.133: v2(114.81,76.96) 115.82,75.95 115.82,72.01 114.81,70.99 110.24,70.99 109.09,69.85 102.86,69.85 97.26,64.26 74.67,64.26 72.57,62.16 66.48,62.16 65.49,61.17 54.95,61.17 v2(54.23,60.45)
  BOTTOM w0.127: v2(54.23,60.45) 54.23,60.07 54.1,59.94 54.1,53.47 54.86,52.7 54.86,51.31 52.32,48.77 v2(52.32,48.31)
SWP1: length 5.2
  TOP w0.127: J8.1 140.59,81.28 SW1.1
  BOTTOM w0.127: J8.1 R258.2
SWP2: length 4.9
  TOP w0.127: J8.3 139.88,82.55 141.6,82.55
  BOTTOM w0.127: R254.2 140.41,81.48 J8.3
SWP3: length 4.6
  TOP w0.127: J8.5 139.17,83.82 SW1.3
  BOTTOM w0.127: J8.5 140.44,83.46 R250.2
SWP4: length 4.6
  TOP w0.127: SW1.4 139.17,85.09 J8.7
  BOTTOM w0.127: R248.2 140.36,85.45 J8.7
SWP5: length 4.9
  TOP w0.127: J8.9 139.88,86.36 SW1.5
  BOTTOM w0.127: J8.9 138.86,87.38 R244.2
SWP6: length 5.2
  TOP w0.127: J8.11 140.59,87.63 SW1.6
  BOTTOM w0.127: R240.2 J8.11
TAS_LRCLK_2INM: length 10.2
  TOP w0.127: C100.1 41.15,83.69 v2(40.89,83.95) 40.26,84.58 36.83,84.58 36.64,84.39 U28.14
  BOTTOM w0.127: R256.1 41.15,83.69 v2(40.89,83.95)
TAS_MCLK_3INM: length 12.9
  TOP w0.127: C104.1 41.66,82.04 41.66,82.55 v2(41.4,82.8) 34.8,82.8 34.48,83.12 U28.12
  BOTTOM w0.127: v2(41.4,82.8) 42.67,81.53 RJ29.2
TAS_SCLK_2INP: length 5.6
  TOP w0.127: U28.13 36.58,83.76 v2(36.64,83.69) C99.1
  BOTTOM w0.127: R257.1 v2(36.64,83.69)
TAS_SDIN1A_1INP: length 5.7
  TOP w0.127: U28.15 36.2,85.03 v2(36.64,85.47) C94.1
  BOTTOM w0.127: R253.1 v2(36.64,85.47)
TAS_SDIN2A_1INM: length 10.7
  TOP w0.127: U28.16 35.88,85.66 36.58,86.36 40.39,86.36 40.83,85.92 v2(40.83,85.47) C95.1
  BOTTOM w0.127: v2(40.83,85.47) R252.1
TAS_SYNC: length 2.3
  TOP w0.127: RJ8.3 RJ9.2
TLIN1: length 22.7
  TOP w0.127: U47.6 v4(111,27.52) R154.2
  BOTTOM w0.127: J17.10 125.15,24.89 113.63,24.89 v4(111,27.52)
TRD1_N: length 4
  TOP w0.112: C233.1 119.89,26.42 119.89,26.41 119.81,26.34 119.81,24.43 J17.2
TRD1_P: length 4
  TOP w0.112: C232.1 119.46,26.34 119.46,24.26 J17.1
TRD_N: length 2.6
  TOP w0.112: U40.13 119.9,37 119.86,36.96 119.86,35.84 120.33,35.37 L44.3
TRD_P: length 2.7
  TOP w0.112: U40.12 119.4,37 119.51,36.88 119.51,35.94 118.94,35.37 L44.4
TRSTPD: length 4.2
  TOP w0.127: J14.8 v2(120.68,50.04)
  BOTTOM w0.127: RJ26.1 120.43,50.29 v2(120.68,50.04) 120.68,49.18 R330.1
USB1_CS: length 37.2
  TOP w0.127: R10.1 v2(127.25,141.6)
  LY4 w0.133: v2(96.65,147.83) 102.36,147.83 104.52,145.67 v2(111.51,145.67)
  BOTTOM w0.127: v2(111.51,145.67) 115.57,141.6 v2(127.25,141.6) ; v2(96.65,147.83) C262.1 R204.1 R203.2
USB1_DM: length 2.8
  TOP w0.122: U11.14 124.72,150.66 124.83,150.77 124.83,151.96 124.56,152.22 FL2.1
USB1_DP: length 2.8
  TOP w0.122: U11.13 125.22,150.66 125.11,150.77 125.11,151.96 125.37,152.22 FL2.4
USB1_IMON: length 106.9
  TOP w0.127: U11.1 123.04,147.29 122.43,146.69 TP3.1 R6.1 C18.1
  LY4 w0.133: v2(132.21,53.21) 132.21,68.83 130.84,70.2 130.84,82.46 131.44,83.06 131.44,93.98 130.72,94.7 130.72,95.72 130.3,96.14 130.3,100.2 130.05,100.46 130.05,122.68 132.08,124.71 132.08,133.6 v2(132.72,134.24)
  BOTTOM w0.127: v2(132.72,134.24) 131.06,135.89 131.06,140.33 128.52,142.88 127.13,142.88 124.08,145.92 TP3.1 ; R317.2 v2(132.21,53.21)
USB1_STATUS: length 196.5
  TOP w0.127: U11.17 122.57,149.46 v2(122.05,149.99) 121.54,150.5 R2.1 ; U27.K22 v1(86.79,82.43)
  LY4 w0.133: v1(86.79,82.43) 86.4,82.04 85.22,82.04 82.68,79.5 79.46,79.5 74.14,74.17 71.43,74.17 71.16,73.91 71.15,73.91 70.15,72.9 68.83,72.9 67.83,71.89 67.83,70.26 67.04,69.47 66.83,69.47 65.77,69.47 63.49,67.19 47.17,67.19 45.29,69.08 45.29,96.38 44.8,96.87 44.8,99.47 46.05,100.72 46.95,100.72 52.14,105.91 52.14,106.85 52.98,107.7 84.07,107.7 84.84,108.46 97.28,108.46 98.55,109.73 100.2,109.73 113.16,122.68 v2(113.16,147.95)
  BOTTOM w0.127: v2(122.05,149.99) 119,149.99 116.97,147.95 v2(113.16,147.95)
USB1_VBUS_OCN: length 192.4
  TOP w0.127: R3.1 121.79,149.35 v2(122.17,148.97) U11.18 ; v1(87.44,81.13) U27.H21
  LY3 w0.133: v2(43.94,71.63) 44.96,71.63 45.59,70.99 64.01,70.99 64.78,71.76 66.68,71.76 70.99,76.07 73.95,76.07 76.75,78.87 83.31,78.87 85.98,81.53 87.04,81.53 v1(87.44,81.13)
  LY4 w0.133: v2(43.94,71.63) 43.94,72.52 45.03,73.6 45.03,96.27 44.54,96.76 44.54,99.58 45.94,100.98 46.84,100.98 51.88,106.02 51.88,106.96 53,108.08 83.82,108.08 84.58,108.84 97.03,108.84 98.42,110.24 100.2,110.24 112.39,122.43 v2(112.39,146.94)
  BOTTOM w0.127: v2(112.39,146.94) 117.22,146.94 119,148.72 120.27,148.72 120.52,148.97 v2(122.17,148.97)
USB2_DM: length 3.1
  TOP w0.122: U12.5 154.62,151.7 154.43,151.89 154.43,153.16 154.71,153.44 FL1.4
USB2_DP: length 3.1
  TOP w0.122: U12.6 153.99,151.7 154.15,151.87 154.15,153.19 153.9,153.44 FL1.1
USB_AC_TXN0: length 2
  TOP w0.122: C14.2 133.1,148.46 133.1,148.89 133.38,149.17 FL6.4
USB_AC_TXP0: length 2
  TOP w0.122: FL6.1 132.56,149.17 132.82,148.92 132.82,148.44 C13.2
VAUDIO_9V0: length 20.4
  TOP w0.305: U44.16 153.43,38.6 v2(153.29,38.73) ; 153.42,39.06 TP45.1 152.73,39.75
  LY4 w0.305: TP45.1 154.1,39.75 ; TP45.1 152.73,39.75 ; TP45.1 153.42,39.06
  BOTTOM w0.305: C484.1 8.76,50.67 9.02,50.93 9.02,50.93 v2(9.02,50.95) 9.76,51.69 R314.1 ; C510.1 8.76,39.24 9.02,39.5 9.02,39.5 v2(9.02,39.52) 9.76,40.26 R352.1 ; R399.2 v2(12.57,15.37) ; C533.1 8.76,16.38 9.02,16.64 9.02,16.64 v2(9.02,16.66) 9.76,17.4 R395.1 ; C528.1 8.76,27.81 9.02,28.07 9.02,28.07 v2(9.02,28.09) 9.76,28.83 R385.1 ; R326.2 v2(12.57,49.66) ; R366.2 v2(12.57,38.23) ; R392.2 v2(12.57,26.8) ; R364.1 v2(153.29,38.73) ; R304.2 v2(12.57,61.09) ; C445.1 8.76,62.1 9.02,62.36 9.02,62.36 v2(9.02,62.38) 9.76,63.12 R293.1
VBIAS_ERR: length 108.1
  TOP w0.127: v2(148.72,42.93) 155.45,42.93 159.51,38.86 R135.2 158.75,37.97 158.18,37.4 U44.9 ; U27.F6 v1(98.49,79.18)
  LY3 w0.133: v1(98.49,79.18) 100.33,77.34 102.49,77.34 104.51,75.32 116.58,75.32 117.47,74.42 125.09,74.42 125.96,73.56 129.82,73.56 130.56,74.3 133.35,74.3 133.65,74 135.21,74 135.46,73.75 135.81,73.75 136.11,74.04 139.32,74.04 139.79,74.51 145.88,74.51 146.56,75.18 v2(150.2,75.18)
  BOTTOM w0.127: v2(150.2,75.18) 150.2,63.72 149.22,62.74 148.08,62.74 145.29,59.94 145.29,49.53 148.72,46.1 v2(148.72,42.93)
VBIAS_SNS_SEL: length 113.1
  TOP w0.127: v2(157.35,30.02) 157.35,30.1 157.33,30.12 U44.7 ; U27.N5 v1(98.49,84.38)
  LY3 w0.133: v2(117.09,84.62) 117.06,84.62 116.52,84.08 114.42,84.08 113.79,84.71 111.12,84.71 110.65,84.23 105.32,84.23 105.03,83.95 101.85,83.95 100.81,84.99 99.09,84.99 v1(98.49,84.38)
  BOTTOM w0.127: 158.12,29.72 157.66,29.72 v2(157.35,30.02) 156.66,29.34 155.57,29.34 150.88,34.04 150.88,38.48 148.21,41.15 148.21,45.97 144.91,49.28 144.91,60.07 149.73,64.9 149.73,71.5 147.83,73.41 147.83,76.07 146.43,77.47 133.73,77.47 132.46,78.74 131.06,78.74 130.56,79.25 122.43,79.25 117.09,84.58 v2(117.09,84.62)
VCAM_9V0: length 6.7
  TOP w0.305: U44.14 154.73,38.65 154.9,38.65 v2(155.03,38.78) ; TP46.1 155.63,39.75 ; TP46.1 154.94,40.44 ; TP46.1 154.94,39.06
  BOTTOM w0.305: TP46.1 154.94,40.44 ; TP46.1 155.63,39.75 ; TP46.1 154.94,39.06 ; v2(155.03,38.78) 155.07,38.74 155.07,38.73 155.45,38.35 R363.1
  vias: v2(167,26.03) v2(168.27,26.29)
VCAP_VBBLDO_DSP: length 5
  TOP w0.254: U27.F8 v1(96.54,79.83)
  BOTTOM w0.381: C388.1 96.82,77.11 96.54,77.4 v1(96.54,79.83)
VCAP_VBBLDO_GPU: length 5.5
  TOP w0.254: U27.T7 v1(97.19,86.98)
  BOTTOM w0.254: v1(97.19,86.98) 97.47,86.78 98.14,86.78 98.3,86.61
  BOTTOM w0.381: C329.1 99.79,86.71 99.69,86.61 98.3,86.61
VCAP_VBBLDO_IVA: length 6.9
  TOP w0.254: U27.G14 92.31,80.81 v1(92.64,80.48)
  LY4 w0.254: v4(90.93,75.97) 91.57,75.97 91.78,76.17 92.83,77.2 92.83,80.3 v1(92.64,80.48)
  BOTTOM w0.305: v4(90.93,75.97) 90.93,75.44 C395.1
VCAP_VBBLDO_MPU: length 5.7
  TOP w0.254: U27.F17 v1(90.04,79.83)
  BOTTOM w0.254: C394.1 89.23,76.15 90.44,77.36 90.5,77.45 90.5,79.37 v1(90.04,79.83)
VCAP_VDDRAM_CORE1: length 6.3
  TOP w0.102: v1(87.44,87.63) 87.44,87.1 ; 87.55,86.98 88.01,86.98
  TOP w0.152: 87.44,87.1 87.55,86.98
  TOP w0.254: 88.01,86.98 U27.U20
  BOTTOM w0.254: C322.1 84.61,87.6 85.03,87.19 87,87.19 v1(87.44,87.63)
VCAP_VDDRAM_CORE3: length 7
  TOP w0.102: v1(97.84,83.73) 97.84,83.19 ; 97.74,83.08 97.28,83.08
  TOP w0.203: 97.84,83.19 97.74,83.08
  TOP w0.254: 97.28,83.08 97.1,82.94 U27.K7
  BOTTOM w0.203: 100.71,83.31 98.26,83.31 v1(97.84,83.73)
  BOTTOM w0.254: 100.71,83.31 101.22,82.81 C358.1
VCAP_VDDRAM_CORE4: length 13.5
  TOP w0.102: v1(88.74,80.48) 88.74,80.48
  TOP w0.254: 88.74,80.48 U27.G19
  LY3 w0.305: v2(87.46,69.43) 87.76,69.72 88.14,69.72 88.65,70.23 88.65,80.39 v1(88.74,80.48)
  BOTTOM w0.254: v2(87.46,69.43) 87.46,69 87.76,68.71 C412.1
VCAP_VDDRAM_DSP: length 7.9
  TOP w0.102: 96.54,84.26 96.54,83.74
  TOP w0.254: 96.54,83.74 U27.L7 ; 96.54,84.26 96.54,84.38 v1(96.54,84.38)
  BOTTOM w0.254: 100.33,84.71 100.22,84.82 96.97,84.82 v1(96.54,84.38)
  BOTTOM w0.406: 100.33,84.71 101.22,83.82 C334.1
VCAP_VDDRAM_GPU: length 6.5
  TOP w0.254: U27.V7 v1(97.19,88.28)
  BOTTOM w0.254: v1(97.19,88.28) 97.19,87.6 97.58,87.2 98.35,87.2 98.43,87.12
  BOTTOM w0.381: C320.1 99.69,87.76 99.06,87.12 98.43,87.12
VCAP_VDDRAM_IVA: length 12.9
  TOP w0.254: U27.G12 v1(93.29,80.48)
  LY3 w0.305: v1(93.29,80.48) 92.84,80.03 92.84,80.03 92.83,80.02 92.83,77.7 92.84,77.69 92.84,77.35 94.08,76.11 94.08,70.86 94.74,70.2 v2(94.74,69.74)
  BOTTOM w0.254: 94.74,69.74 94.74,69.72 94.72,69.7
  BOTTOM w0.406: C426.1 94.72,69.7 ; 94.74,69.74 v2(94.74,69.74)
VCAP_VDDRAM_MPU: length 3.7
  TOP w0.254: U27.G18 v1(89.39,80.48)
  BOTTOM w0.254: v1(89.39,80.48) 88.52,79.62 88.52,78.11 C374.1
VCNTL_3V3: length 21.6
  TOP w0.305: U32.34 86.97,51.89 v2(87.4,51.46) ; Q8.3 v2(85.64,39.24)
  LY3 w0.305: v2(85.64,39.24) 88.9,39.24 89.66,40 89.66,43.18 90.04,43.56 90.04,45.21 87.4,47.85 v2(87.4,51.46)
  BOTTOM w0.305: C481.1 87.41,51.45 v2(87.4,51.46) ; R373.2 v2(85.64,39.24) R378.2
VDA_COREGMACVID_FIL1V8: length 20.7
  TOP w0.254: U27.L9 v1(95.24,83.73) U27.L10 v1(95.24,83.08) U27.K10
  BOTTOM w0.254: 97.77,83.08 97.92,82.93 100.08,82.93 100.17,82.84
  BOTTOM w0.305: 97.77,83.08 v1(95.24,83.08) v1(95.24,83.73)
  BOTTOM w0.381: E5.3 110.58,81.16 C372.1 ; 100.17,82.84 100.97,82.04 C359.1
  BOTTOM w0.406: C359.1 106.17,81.03 109.47,81.03 109.7,81.25 E5.3
VDA_CSI_FIL1V8: length 16.3
  TOP w0.254: U27.T6 v1(97.84,86.33)
  BOTTOM w0.203: v1(97.84,86.33) 98.08,86.09 100.1,86.09
  BOTTOM w0.305: 101.48,85.98 101.37,86.09 100.1,86.09
  BOTTOM w0.381: C324.1 112.51,86.39 E3.3 109.92,86.39 109.39,85.86 106.43,85.86 C333.1 105.79,85.36 105.17,85.98 101.48,85.98
VDA_DDRDBGGPUPER_FIL1V8: length 22.8
  TOP w0.254: U27.N9 v1(95.24,85.03) U27.N10 v1(95.24,84.38) U27.M10
  LY3 w0.203: v1(95.24,84.38) 95.81,84.38 96.71,85.28 101.28,85.28
  LY3 w0.381: 101.28,85.28 105.86,85.28 106.43,84.71 108.84,84.71 109.38,85.25 v2(111.63,85.25)
  BOTTOM w0.254: C340.1 v1(95.24,85.03)
  BOTTOM w0.305: v1(95.24,85.03) v1(95.24,84.38)
  BOTTOM w0.406: C343.1 112.03,84.85 v2(111.63,85.25) 111.32,84.94 E4.3
VDA_MPU_ABE_FIL1V8: length 18.9
  TOP w0.254: U27.K16 v1(90.69,83.08) U27.L16
  LY4 w0.305: 90.52,80.04 90.49,80.04 89.58,80.95 89.58,81.32 90.69,82.43 90.69,82.48
  LY4 w0.381: 90.69,82.48 v1(90.69,83.08) ; 90.52,80.04 90.8,79.75 90.8,77.47 86.13,72.79 v2(85.24,72.79)
  BOTTOM w0.254: C349.1 90.59,83.19 v1(90.69,83.08)
  BOTTOM w0.406: v2(85.24,72.79) 84.83,72.38 E7.3 84.74,71.8 v2(84.74,70.88) 84.71,70.84 C407.1
VDA_OSC_FIL1V8: length 16.1
  TOP w0.254: U27.Y13 v1(93.29,88.93) U27.W13
  BOTTOM w0.254: v1(93.29,88.93) C309.1 93.73,89.62 93.73,89.97 94.14,90.39
  BOTTOM w0.381: E1.3 102.21,97.69 102.12,97.78 C286.1 101.27,96.7 97.66,93.09 95.88,93.09 94.61,91.82 94.61,90.86 94.14,90.39
VDA_PCIE_FIL1V8: length 25.1
  TOP w0.254: U27.W15 v1(91.99,88.93) U27.Y15 ; U27.W11 v1(93.94,88.93) U27.Y11
  BOTTOM w0.254: C308.1 v1(91.99,88.93)
  BOTTOM w0.381: v1(93.94,88.93) 94.36,89.36 94.36,89.68 94.98,90.3 95.38,90.3 95.88,90.8 95.88,91.69 96.67,92.48 97.94,92.48 99.82,94.36 107.19,94.36 109.31,92.24 E2.3
  BOTTOM w0.508: C301.1 112.64,92.24 E2.3
VDA_PHY_1V8: length 164.6
  TOP w0.254: U27.W8 v1(96.54,88.93) U27.Y8 v1(95.89,88.93) U27.Y9
  TOP w0.305: U32.21 80.37,54.88 v2(80.14,55.12)
  TOP w0.508: v2(52.58,59.69) 50.67,61.59 49.28,61.59 46.23,64.64 46.23,73.02 47.62,74.42 47.62,96.27 48.26,96.9 v2(48.26,103.38)
  LY3 w0.508: v2(48.26,103.38) 49.15,104.27 49.15,106.43 50.04,107.31 55.5,107.31 56.9,105.92 87.76,105.92 94.61,99.06 94.61,95.25 95,94.87 95,93.09
  LY4 w0.508: v2(80.14,55.12) 78.61,55.12 78.11,54.61 68.96,54.61 67.56,53.21 65.53,53.21 64.77,53.97 64.77,59.18 64.01,59.94 61.21,59.94 60.96,59.69 v2(52.58,59.69)
  BOTTOM w0.305: v2(80.14,55.12) 79.63,55.63 C465.1 ; 97.79,90.84 97.19,90.24 C306.1 97.19,90.23 96.54,89.58 v1(96.54,88.93)
  BOTTOM w0.381: C302.1 101.51,91.02 103.12,89.41 109.35,89.41 ; 109.35,89.41 109.35,89.03 109.75,88.62 E3.1 ; 109.35,89.41 109.35,89.45 109.9,90 E2.1 ; v1(96.54,88.93) v1(95.89,88.93)
  BOTTOM w0.508: C302.1 100.51,91.13 100.2,91.44 98.39,91.44 97.79,90.84
VDA_PLL_1V8: length 228.7
  TOP w0.254: v1(88.09,86.33) U27.R20 ; v2(86.46,60.55) 86.47,60.55 U32.4
  TOP w0.381: v4(82.59,71.14) 82.59,70.7 83.82,69.47 83.82,68.2 84.84,67.18 84.84,65.28 86.46,63.65 v2(86.46,60.55)
  TOP w0.508: v2(45.47,67.56) 45.47,73.41 46.86,74.8 46.86,96.9 47.5,97.54 v2(47.5,103)
  LY3 w0.508: v2(86.46,60.55) 86.46,63.02 84.58,64.9 74.93,64.9 74.49,65.34 72.46,65.34 72.39,65.41 72.01,65.41 69.72,67.69 45.59,67.69 v2(45.47,67.56) ; v2(93.09,102.23) 88.52,106.81 57.28,106.81 55.88,108.2 49.53,108.2 47.5,106.17 v2(47.5,103)
  LY4 w0.381: v4(82.59,71.14) 83.08,71.63 83.97,71.63 84.24,71.63 84.24,71.63 85.72,71.63 86.32,71.03 v2(87,71.03)
  BOTTOM w0.254: C443.1 86.49,60.58 v2(86.46,60.55) ; C331.1 83.64,86.81 87.69,86.81 88.09,86.41 v1(88.09,86.33)
  BOTTOM w0.381: C331.1 83.17,85.97 82.8,85.6 81.41,85.6 80.52,84.71 80.52,82.93 78.87,81.28 78.87,75.91 81.28,73.5 C406.1 82.58,71.12 v4(82.59,71.14)
  BOTTOM w0.406: E7.1 v4(82.59,71.14) ; E6.1 v2(87,71.03)
  BOTTOM w0.508: v2(93.09,102.23) 99.06,102.23 101.37,99.92 E1.1 104.65,99.92 105.23,99.34 105.23,97.46 106.81,95.88 112.27,95.88 113.92,94.23 113.92,82.68 ; 113.92,82.68 113.87,82.63 v2(111.35,82.63) 111.28,82.7 E4.1 v2(109.73,82.7) ; 113.92,82.68 113.92,80.14 112.78,78.99 v2(111.38,78.99) 111.35,79.02 E5.1 109.63,79.02 v2(109.6,78.99)
VDA_SDIO_DV: length 214.9
  TOP w0.254: U27.P8 v1(95.89,85.03) U27.N8 ; U32.23 81.06,53.88 80.77,53.59 v2(80.77,52.96)
  TOP w0.305: v2(103,84.58) 103.76,83.82 104.52,83.82 105.24,83.1 106.09,83.1 106.2,83.21 109.94,83.21 111.11,82.04 v2(114.55,82.04)
  LY3 w0.305: v2(150.11,101.98) 150.11,102.59 149.81,102.9 149.38,102.9 148.21,101.73 147.88,101.73 147.82,101.66 147.13,101.66 147.07,101.73 143.76,101.73 v2(143.38,102.11) 142.71,102.78 142.15,102.78 v2(141.48,102.11) 141.1,102.11 140.46,102.74 v2(137.41,102.74) 135.51,102.74 131.83,106.43 v2(124.08,106.43) ; v2(92.33,62.99) 92.33,56.26 90.17,54.1 88.39,54.1 87.63,53.34 81.15,53.34 v2(80.77,52.96) ; v2(126.36,80.81) 125.95,80.39 120.02,80.39 118.49,81.91 114.68,81.91 v2(114.55,82.04)
  LY4 w0.305: v2(92.33,62.99) 111.12,62.99 113.54,65.41 113.54,68.96 116.2,71.63 116.2,76.45 115.19,77.47 115.19,81.41 v2(114.55,82.04) ; v2(148.46,115.7) 147.57,115.7 147.07,116.2 139.19,116.2 138.3,115.32 138.3,106.81 137.41,105.92 v2(137.41,102.74) ; v2(126.36,80.81) 126.36,88.39 124.46,90.3 124.46,96.39 124.08,96.77 v2(124.08,106.43)
  BOTTOM w0.254: v1(95.89,85.03) 96.07,85.22 97.14,85.22 97.14,85.22 100.2,85.22 100.33,85.35
  BOTTOM w0.305: R230.1 v2(141.48,102.11) ; R229.1 R231.1 v2(150.11,101.98) ; R228.1 v2(143.38,102.11) ; R410.1 132.97,125.73 124.08,116.84 v2(124.08,106.43) ; R227.1 v2(148.46,115.7) R226.1 ; C477.1 v2(80.77,52.96)
  BOTTOM w0.381: C345.1 102.75,84.83 v2(103,84.58)
  BOTTOM w0.406: 100.33,85.35 102.62,85.35 C345.1
VDA_USB_3V3: length 164.2
  TOP w0.254: U27.AA10 v1(95.24,89.58) U27.Y10
  TOP w0.305: U32.7 84.97,60.45 84.99,60.47 v2(84.99,61.15)
  TOP w0.508: v2(44.7,66.93) 44.7,73.79 46.1,75.18 46.1,96.65 45.94,96.81 45.94,98.14 46.74,98.93 v2(46.74,102.49)
  LY3 w0.508: v2(44.7,66.93) 69.47,66.93 71.8,64.6 73.83,64.6 74.3,64.13 82.42,64.13 84.99,61.57 v2(84.99,61.15) ; v2(96.14,97.54) 96.14,100.46 88.9,107.7 57.66,107.7 56.26,109.09 48.26,109.09 46.74,107.57 v2(46.74,102.49)
  LY4 w0.508: v2(96.14,97.54) 95.38,97.54 94.49,96.65 94.49,95.5 94.74,95.25 94.74,93.22 94.61,93.09 94.61,90.21 v1(95.24,89.58)
  BOTTOM w0.305: C440.1 84.99,61.7 v2(84.99,61.15)
  BOTTOM w0.381: 96.14,98.3 v2(96.14,97.54)
  BOTTOM w0.406: C281.1 98.93,95.25 97.54,93.85 R236.2 R237.1
  BOTTOM w0.508: 96.14,98.3 98.86,98.3 C281.1
VDA_VIDEO_FIL1V8: length 15.7
  TOP w0.254: U27.L14 v1(91.99,83.08) U27.K14
  BOTTOM w0.254: v1(91.99,83.08) 91.88,82.9 91.88,82.89 91.62,82.63 91.61,82.63 C364.1 91.39,81.99 90.68,81.28 90.68,80.01 90.91,79.78 90.91,77.06 89.93,76.09
  BOTTOM w0.305: 89.93,76.09 89.93,73.21 89.5,72.78 v2(89.24,72.78)
  BOTTOM w0.406: v2(89.24,72.78) E6.3 89.24,69.93 C408.1
VDISP_16V0: length 4.3
  TOP w0.305: TP47.1 143.18,39.24 ; TP47.1 141.81,39.24 ; TP47.1 142.49,38.56
  LY4 w0.305: 142.49,38.56 TP47.1 143.18,39.24
  BOTTOM w0.305: C462.1 v2(165.23,56.52)
  vias: v2(166.12,55.58) v2(167.13,55.58) v3(142.37,37.46) v3(144.14,38.99)
VEXP_1V8A: length 2.3
  TOP w0.305: v2(70.87,14.22) R171.2
  BOTTOM w0.305: J19.113 71.08,14.01 v2(70.87,14.22)
VEXP_1V8B: length 2.3
  TOP w0.305: v2(72.01,14.22) R170.2
  BOTTOM w0.305: J19.112 71.68,13.9 v2(72.01,14.22)
VEXP_3V3A: length 2.2
  TOP w0.305: v2(70.87,19.56) R188.1
  BOTTOM w0.305: v2(70.87,19.56) 71.08,19.34 J19.8
VEXP_3V3B: length 2.3
  TOP w0.305: v2(72.01,19.56) R187.1
  BOTTOM w0.305: J19.9 71.68,19.23 v2(72.01,19.56)
VEXP_5V0A: length 2
  TOP w0.305: v2(66.93,19.43) R186.1
  BOTTOM w0.305: J19.1 66.89,19.39 v2(66.93,19.43)
VEXP_5V0B: length 2.3
  TOP w0.305: R185.1 69.22,18.8 v2(69.22,19.56)
  BOTTOM w0.305: v2(69.22,19.56) 69.29,19.49 J19.5
VEXP_5V0C: length 2.1
  TOP w0.305: R167.2 68.33,13.84 v2(68.45,13.97)
  BOTTOM w0.305: J19.117 68.69,13.74 v2(68.45,13.97)
VEXP_5V0D: length 2.2
  TOP w0.305: v2(69.45,14.08) 69.45,13.22 R166.2
  BOTTOM w0.305: v2(69.45,14.08) 69.29,13.91 J19.116
VHDMI_5V0: length 18.5
  TOP w0.203: v2(116.08,151.76) 115.77,152.07 U17.12 ; v2(109.47,159.38) 109.42,159.44 P1.18 109.42,160.92
  LY4 w0.305: v2(109.47,159.38) 116.08,159.38 116.84,158.62 116.84,152.53 v2(116.08,151.76)
  BOTTOM w0.305: C268.1 v2(116.08,151.76)
VIO_3V3: length 352.6
  TOP w0.102: 88.73,83.61 88.74,83.6 88.74,83.21 ; 91.25,80.48 90.78,80.48
  TOP w0.127: 90.78,80.48 90.77,80.49
  TOP w0.203: U27.M19 88.73,83.72 88.73,83.61 ; 88.74,83.21 88.74,83.08 U27.K19 88.83,82.52 v1(88.74,82.43) ; U17.23 115.77,157.55 v2(116.08,157.86)
  TOP w0.254: 90.77,80.49 U27.G17 v1(90.04,81.13) U27.H17 ; U27.H15 91.92,81.12 U27.G15 91.25,80.48 ; U70.2 v2(159.13,130.69) ; U25.22 v2(153.94,84.99) ; U27.N7 v1(97.19,84.38) U27.M7 ; U27.N19 v1(89.39,84.38) U27.M19 ; U27.K8 v1(95.89,82.43) U27.J8 96.47,81.85 v1(96.54,81.78) 96.86,82.11 U27.J7 96.86,82.11 v1(97.19,82.43) ; U40.11 118.89,36.73 v2(118.87,36.7) ; v2(159,129.92) 159,129.93 158.75,130.19 U70.1 ; U27.J19 v1(88.74,82.43) ; C140.1 C141.1
  TOP w0.305: U31.F8 v2(127.21,69.42) ; v2(54.86,56.13) C152.1 C151.1 53.72,55.75 51.77,53.8 U34.24 ; U22.8 36.28,96.74 v2(35.94,96.39) ; v2(32.38,57.47) C137.1 C136.1 31.37,56.9 31.07,56.6 U36.47 ; R169.2 v2(93.73,14.86) ; R2.2 v2(119.38,150.5) ; 82.93,18.54 82.93,18.92 82.55,19.3 v2(82.55,19.68) ; R68.1 165.74,78.1 161.93,81.91 v2(156.59,81.91) ; TP10.1 104.39,120.83 ; TP10.1 105.08,120.14 ; TP10.1 104.39,119.46 ; 95.25,80.49 95.23,80.49 U27.G10 ; 95.25,80.49 U27.G9 ; 95.25,80.49 v1(95.58,79.73) ; U34.27 49.38,56.74 C147.1 C148.1 v2(50.42,56.13) ; v2(125.21,39.37) 125.78,39.37 C189.1 125.78,38.61 v2(125.22,38.61) ; U13.5 v2(147.72,144.92) ; v2(78.87,17.08) 78.87,18.16 79.25,18.54 79.76,18.54 ; L16.1 v2(142.62,74.93) ; U31.F3 v2(121.2,69.42) ; L17.2 v2(149.22,72.77) ; v2(161.16,130.18) 161.16,129.67 C546.1 160.4,129.67 v2(160.4,130.18) ; U40.22 123.3,39.88 v2(124.08,39.88) ; C140.1 35.81,57.66 35.05,56.9 33.91,56.9 33.02,56.01 32.77,56.01 32.57,55.81 U36.44 ; R105.1 v2(149.1,61.85) ; R412.1 160.78,133.22 v2(159.64,133.22) ; C128.1 v2(151.13,61.85) ; U31.F2 v2(120.2,69.42) ; RJ14.3 v2(95.38,15.87) ; R308.1 126.49,55.12 v2(126.24,54.86) ; R122.2 v2(53.97,52.07) ; U31.F5 v2(123.21,69.42) ; U12.9 152.72,144.21 v2(152.53,144.02) ; R71.1 v2(70.36,77.22) ; U31.F7 v2(126.21,69.42) ; v2(116.97,35.19) 116.97,34.62 C212.1 116.2,34.62 v2(116.2,35.18) ; R135.1 v2(159.51,36.13) ; U31.F4 v2(122.2,69.42) ; L63.1 v2(150.62,60.71) ; U14.5 v2(150.76,144.92) ; R33.1 v2(116.08,149.99) ; U31.F9 v2(128.21,69.42) ; U31.F6 v2(125.21,69.42) ; R27.2 v2(110.62,155.07) ; C141.1 v2(36.83,57.47) ; R3.2 v2(119.38,149.35) ; U25.23 v2(153.98,83.89) ; RJ1.1 v2(127.83,150.62)
  TOP w0.406: RJ10.3 v2(39.62,86.99) ; RJ8.1 v2(36.07,88.27) ; RJ6.3 v2(39.62,90.8) ; RJ7.3 v2(39.62,89.53)
  TOP w0.508: R149.1 v3(148.84,26.92) ; C83.1 18.92,98.46 v2(18.88,98.42) ; R55.1 v2(13.33,100.2) ; C114.1 v2(109.35,73.79) C118.1 ; C44.1 139.83,123.52 C49.1 139.84,122.04 U21.19 ; C44.1 v2(140.72,123.57) ; C44.1 v2(139.78,124.84) ; RJ13.1 v2(63.18,30.35) ; C119.1 v2(110.87,74.17) ; R158.1 v3(138.68,24.13) ; R40.1 v2(61.47,117.35) ; C120.1 112.9,73.91 v2(113.16,74.17)
  LY3 w0.305: v2(70.36,77.22) 73.53,77.22 79.38,83.06 v2(79.76,83.06)
  LY4 w0.305: v2(89.53,164.59) 90.17,163.96 92.52,163.96 v2(93.22,164.66) 94.17,164.66 94.74,164.08 113.28,164.08 118.24,159.13 118.24,156.21 v2(117.6,155.57)
  LY4 w0.381: v1(88.74,82.43) 88.74,82.73 89.19,83.19 89.79,83.19 90.04,83.51 90.04,84.08 89.74,84.38 v1(89.39,84.38)
  LY4 w0.508: v3(138.68,24.13) 138.68,24.89 139.45,25.65 148.25,25.65 148.84,26.25 v3(148.84,26.92)
  LY5_PWR w0.305: TP10.1 104.39,120.83 ; TP10.1 103.71,120.14 ; TP10.1 105.08,120.14 ; TP10.1 104.39,119.46
  BOTTOM w0.254: v2(127.38,92.84) 127.66,93.12 J21.1 ; v2(18.88,98.42) 18.52,98.79 U52.1 ; J21.3 v2(128.66,92.85) 128.16,93.35 J21.2 ; C456.2 C457.2 v2(28.83,58.55) 28.57,58.8 28.57,59.26 ; C455.2 v2(49.15,59.18) 48.89,59.44 48.89,59.9 50.03,59.9 50.11,59.81 50.17,59.81 v2(50.42,59.56) C446.2 ; C507.1 v2(124.08,39.88)
  BOTTOM w0.305: R189.1 v2(93.22,164.66) ; C509.1 125.48,38.35 v2(125.22,38.61) 125.21,38.61 ; U54.5 114.81,61.49 114.53,61.21 v2(113.92,61.21) ; v2(125.21,39.37) 125.46,39.62 C508.1 ; R311.1 R310.1 v2(118.11,52.58) ; v2(134.49,60.32) RJ25.3 RJ24.3 ; v2(117.6,155.57) R216.1 R215.2 ; v2(54.86,56.13) 54.86,56.9 C459.1 ; R212.2 v2(116.08,157.86) 116.33,157.61 C267.1 ; C451.1 36.83,57.78 v2(36.83,57.47) ; v2(148.84,147.19) 149.22,146.81 R200.1 ; C282.1 79.76,83.82 v2(79.76,83.06) ; R241.2 v2(133.48,89.41) ; v2(159.51,36.13) 159.45,36.13 158.37,35.05 152.65,35.05 151.64,36.07 151.64,39.24 149.73,41.15 149.73,45.34 v2(150.11,45.72) R334.1 ; 116.2,35.19 v2(116.2,35.18) 115.95,34.92 C519.1 ; C453.1 32.38,57.78 v2(32.38,57.47) ; R233.2 v2(37.97,101.09) ; v2(156.59,84.2) 156.67,84.13 P9.30 ; RJ20.3 RJ19.3 RJ18.3 v2(132.33,72.39) ; R191.2 v2(89.53,164.59) ; 92.46,93.98 v2(91.63,93.98) ; v2(147.72,144.92) 147.72,145.78 C261.1 ; v2(153.98,83.89) 154.04,83.95 C353.1 ; v2(156.59,83.44) 156.78,83.63 P9.32 ; C518.1 117.22,34.94 v2(116.97,35.19) ; R307.1 122.88,53.47 v2(123.2,53.79) ; R201.1 v2(145.92,146.81) ; v2(120.14,55.88) 120.65,55.37 R312.1 ; C260.1 150.76,145.78 v2(150.76,144.92) ; R242.2 v2(42.54,105.41) R239.2 ; RU2.16 v2(145.4,113.78) 145.16,114.03 C539.2 ; C437.1 128.39,69.6 v2(128.21,69.42) ; v2(50.42,56.13) 50.16,56.39 C461.1 ; R344.1 v2(118.36,45.08) ; v2(139.19,74.8) RJ16.1 RJ17.1 ; v2(144.02,62.86) 143.13,63.75 R297.1 ; RJ22.3 v2(131.57,66.55) ; RJ22.3 RJ23.3 ; RJ22.3 RJ21.3 ; v2(142.24,79.5) R258.1 R254.1 R250.1 ; 35.43,97.28 35.43,96.9 v2(35.94,96.39) ; C435.1 123.39,69.6 v2(123.21,69.42) ; R290.1 v2(148.59,70.1) ; R247.2 v2(132.84,85.47) ; R234.2 v2(37.97,99.82) ; R206.1 v2(153.54,146.69) ; C350.1 v2(39.62,86.99) ; R243.2 v2(132.84,87.5) ; RU1.16 v2(152.01,113.78) ; R313.2 v2(32.26,52.7) ; 153.54,58.42 153.54,58.99 v2(153.32,59.21) ; R329.1 R328.1 v2(122.56,50.04) ; 72.01,77.22 70.36,77.22 v2(70.36,77.22) ; P9.34 v2(156.59,82.63) ; v2(152.53,144.02) C264.1 ; R358.2 R360.2 R365.2 118.49,37.08 v2(118.87,36.7) C511.1 ; R249.1 v2(147.45,84.71) ; R274.1 v2(145.29,72.64) ; P9.36 156.8,82.13 v2(156.59,81.91) ; C517.1 v2(75.82,35.81) ; R342.2 v2(115.23,44.7)
  BOTTOM w0.508: C288.1 v2(107.31,96.9) ; C442.2 v2(113.92,61.21) ; C277.1 v2(106.05,98.17) ; v2(105.03,117.73) 104.65,118.11 101.35,118.11 97.66,114.43 93.6,114.43 85.6,106.43 65.41,106.43 62.48,109.35 62.48,116.33 v2(61.47,117.35)
  vias: v2(77.09,36.83) v2(94.02,94.49) v2(105.16,118.87) v2(114.05,74.17) v2(114.07,73.15) v2(114.05,72.14) v2(115.06,74.17) v2(115.06,73.15) v2(115.06,72.14)
